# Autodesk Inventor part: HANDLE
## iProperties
Author: GJOHNST2
Shininess: 20.0
Length Units: 11272
Angle Units: 11286
Time Units: 11279
Mass Units: 11290
Length Display Precision: 3
Angle Display Precision: 2
Compacted: True
PropertySet Name: _Private Model Information
Created: 2001-11
Part Number: HANDLE
Document SubType Name: Sheet Metal
Designer: GJOHNST2
Control State: 0
Master: False
Checked Out: False
PropertySet Name: Design Tracking Control
Density: 0.0
Volumn: 0.0
Area: 0.0
PropertySet Name: Model Information
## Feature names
1. Bend3
2. Bend6
3. Hole1
4. Plate1
5. Plate2
6. Bend1
7. Plate3
8. Bend2
9. Plate4
10. Bend4
11. Plate5
12. Bend5
